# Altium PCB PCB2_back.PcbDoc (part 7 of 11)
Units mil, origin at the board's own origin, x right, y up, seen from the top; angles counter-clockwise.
Board outline 6299 x 3937 mil, 4 copper layers (TopLayer, GROUND, VCC, BottomLayer); 290 components, 470 nets, 2252 pads, 825 vias.
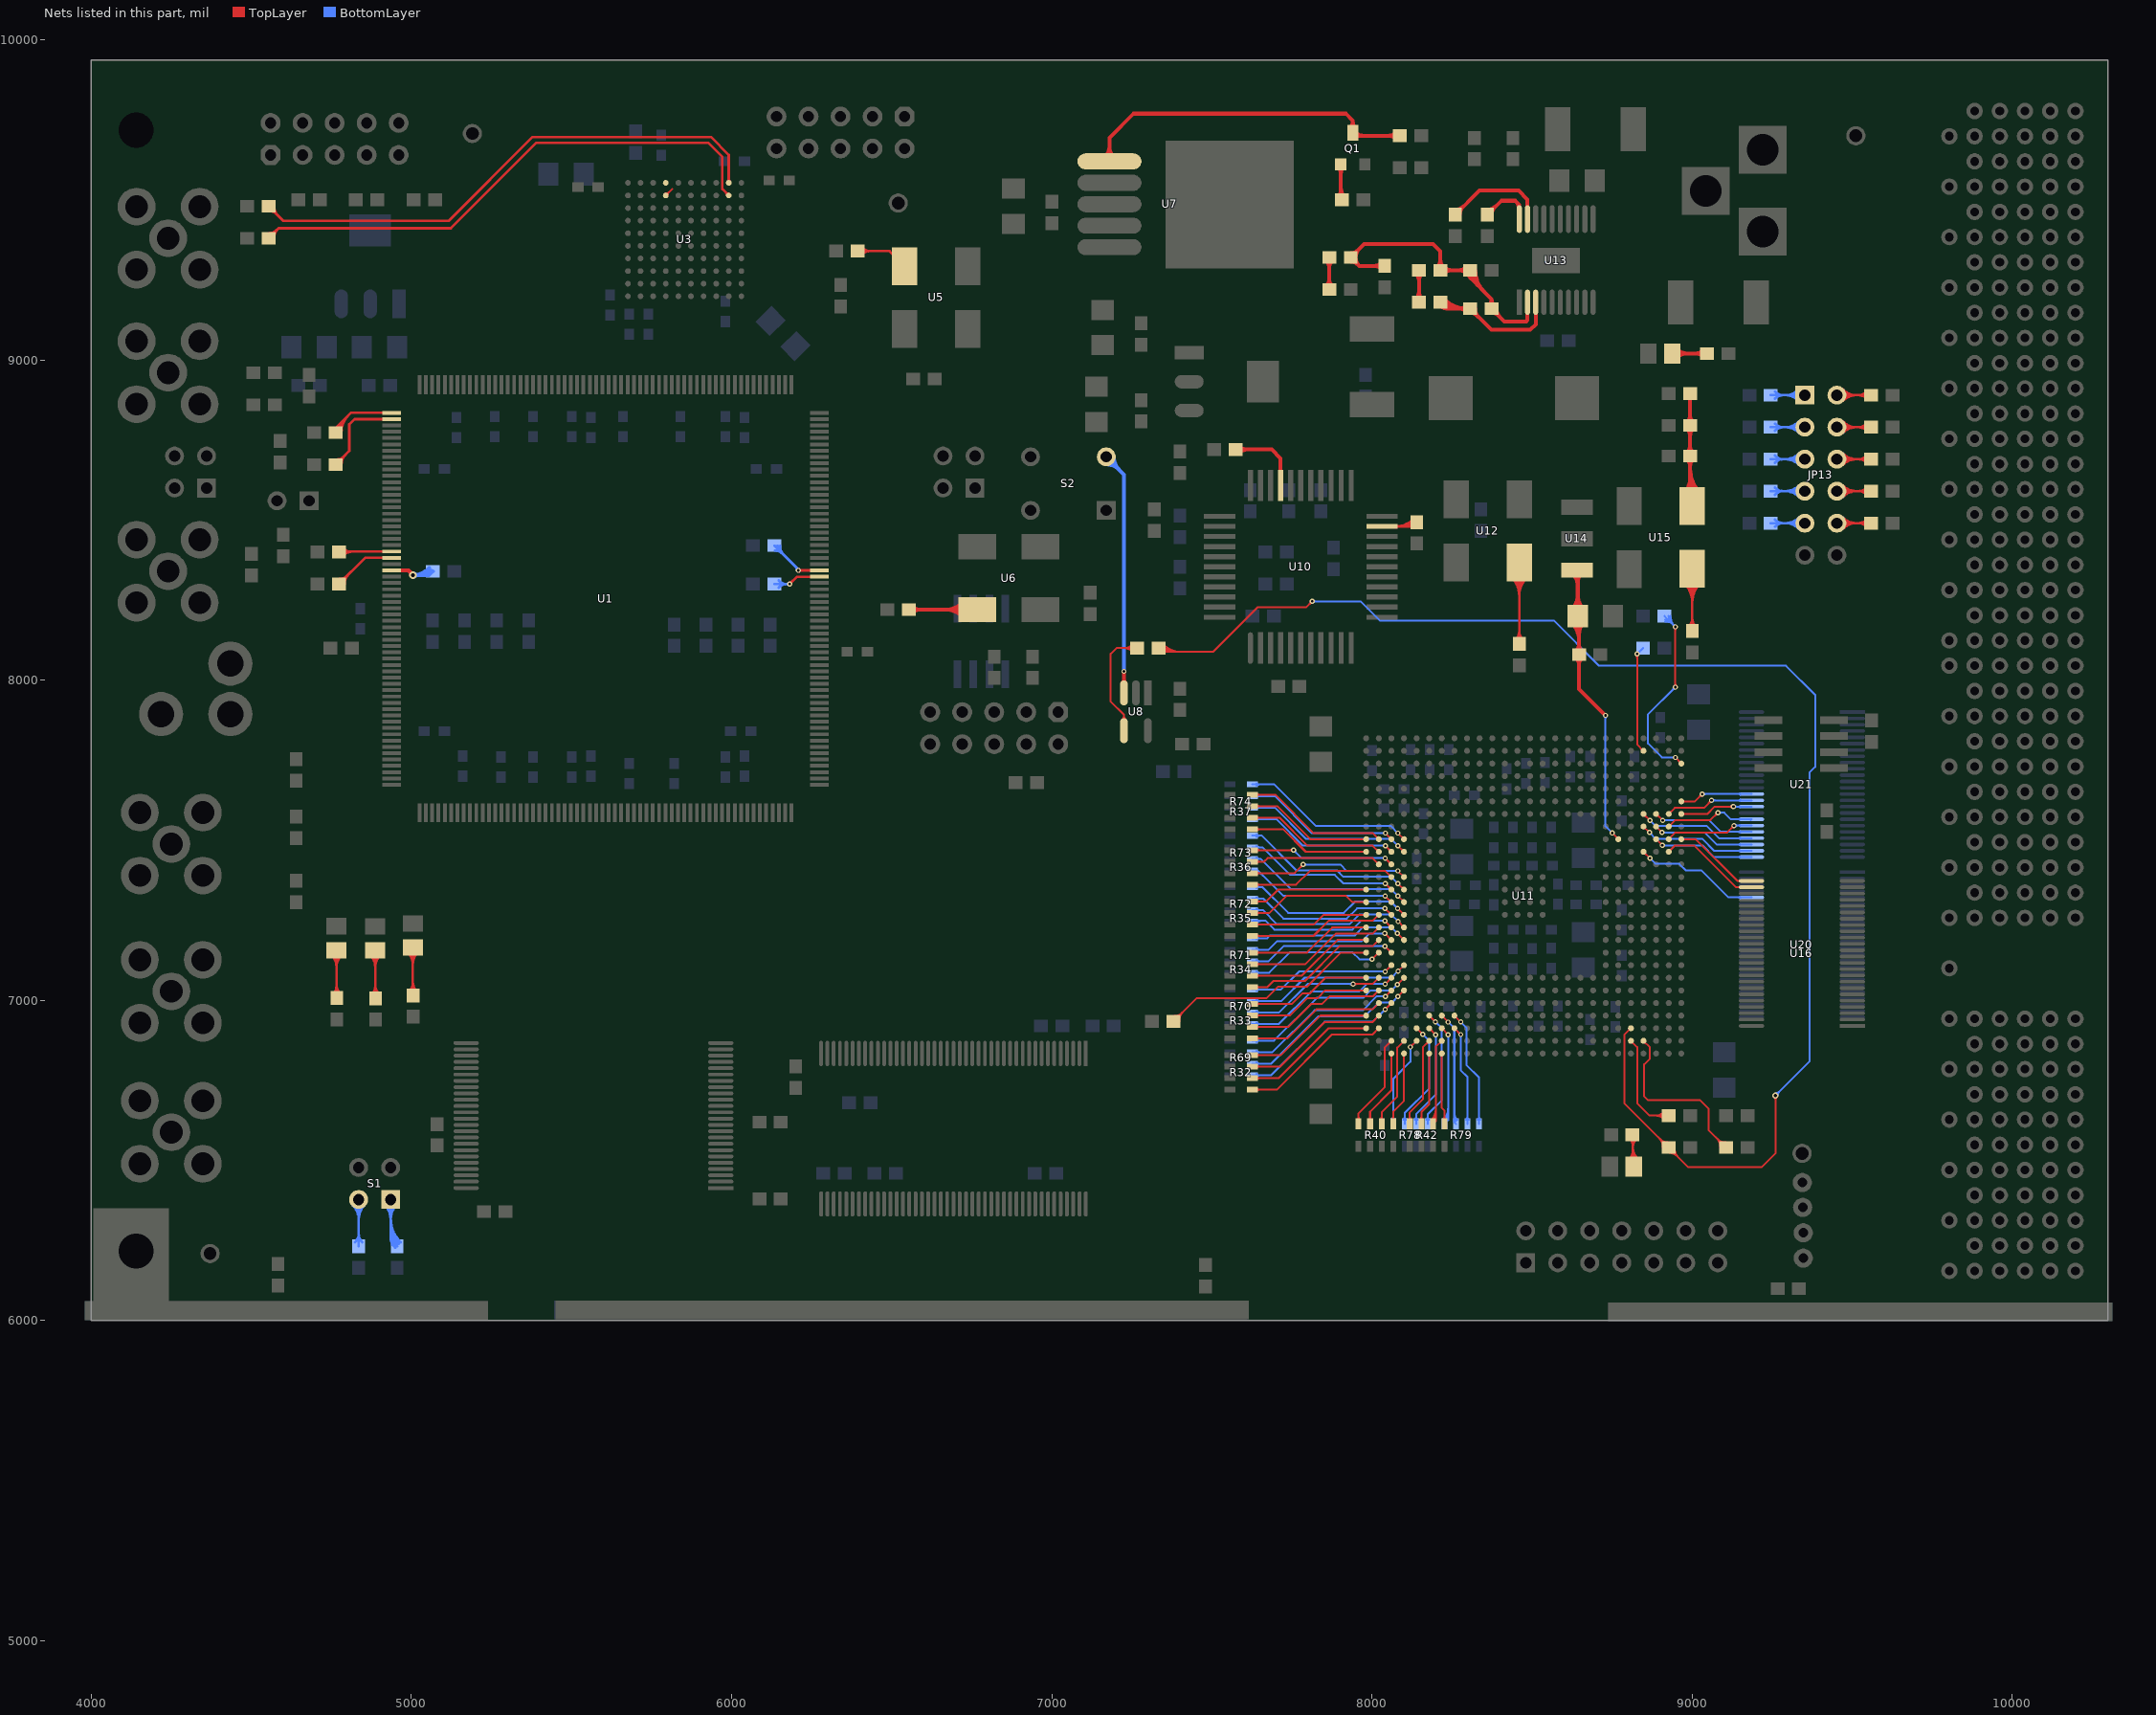
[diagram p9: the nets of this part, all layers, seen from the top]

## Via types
v1: diameter 16, hole 8, TopLayer to BottomLayer, 408 vias
v2: diameter 20, hole 10, TopLayer to BottomLayer, 221 vias
v3: diameter 24, hole 12, TopLayer to BottomLayer, 194 vias
v4: diameter 56.69, hole 56.69, TopLayer to BottomLayer, 2 vias

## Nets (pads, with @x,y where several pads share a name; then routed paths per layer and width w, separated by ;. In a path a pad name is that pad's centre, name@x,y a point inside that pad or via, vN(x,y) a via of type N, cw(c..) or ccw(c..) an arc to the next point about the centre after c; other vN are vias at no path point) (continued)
NetC113_1: C24.1 C25.1 C26.1 R41.1 R48.2 U13.2 | length 1527.5
  TopLayer w12: C24.1@7935.43,9306.31 cw(c7935.43,9278.03) 7955.43,9298.03 ; C24.1@7935.43,9333.69 ccw(c7935.43,9361.97) 7955.43,9341.97 ; C24.1@7949.11,9319.54 ccw(c7982.97,9318.41) 7959.01,9294.45 ; C24.1@7949.12,9320 cw(c7986.91,9320) 7960.19,9346.72 ; R41.1@8030.32,9283.79 ccw(c8006.96,9260.43) 8006.96,9293.46 ccw(c8006.96,9326.5) R41.1@8030.32,9303.14 ; R41.1@8040,9293.46 7960,9293.46 C24.1@7933.46,9320 7975.46,9362 8191,9362 8213.46,9339.54 C25.1@8213.46,9280 R48.2@8306.54,9280 8306.54,9256.46 ; C25.1@8203.79,9289.68 ccw(c8180.43,9313.04) 8213.46,9313.04 ccw(c8246.5,9313.04) C25.1@8223.14,9289.68 ; C25.1@8225.11,9270.32 cw(c8248.47,9246.96) 8248.47,9280 cw(c8248.47,9313.04) C25.1@8225.11,9289.68 ; R48.2@8294.89,9270.32 ccw(c8271.53,9246.96) 8271.53,9280 ccw(c8271.53,9313.04) R48.2@8294.89,9289.68 ; R48.2@8298.19,9280 ccw(c8334.86,9280) 8308.93,9254.07 ; R48.2@8299.77,9268.11 cw(c8293.14,9256.47) 8306.54,9256.47 ; R48.2@8300.22,9269.1 cw(c8290.56,9256.38) 8306.54,9256.38 cw(c8318.49,9256.38) R48.2@8313.83,9267.4 ; R48.2@8310.19,9280 ccw(c8375.83,9280) 8329.41,9233.59 ; R48.2@8313.3,9268.11 ccw(c8319.93,9256.47) 8306.54,9256.47 ; R48.2@8322.19,9280 ccw(c8416.8,9280) 8349.9,9213.1 ; C26.1@8364.62,9170.44 ccw(c8348.44,9189.53) 8373.46,9189.53 ; C26.1@8375.43,9146.31 cw(c8375.43,9118.03) 8395.43,9138.03 ; C26.1@8382.31,9170.44 cw(c8398.49,9189.53) 8373.46,9189.53 ; C26.1@8389.12,9160 ccw(c8426.91,9160) 8400.19,9133.28 ; U13.2@8485.59,9180 8485.59,9123.59 8482,9120 8413.46,9120 C26.1@8373.46,9160 8373.46,9189.54 ; 8306.54,9256.46 8373.46,9189.54
NetC113_2: C25.2 R47.1 | length 203.8
  TopLayer w12: R47.1@8136.86,9189.68 ccw(c8113.5,9213.04) 8146.54,9213.04 ccw(c8179.57,9213.04) R47.1@8156.21,9189.68 ; C25.2@8136.86,9270.32 cw(c8113.5,9246.96) 8146.54,9246.96 cw(c8179.57,9246.96) C25.2@8156.21,9270.32 ; R47.1@8146.54,9180 C25.2@8146.54,9280
NetC118_2: C26.2 R47.2 U13.3 | length 717
  TopLayer w12: R47.2@8208.14,9172.71 ccw(c8238.81,9203.38) 8238.81,9160 ; R47.2@8213.46,9180 8233.46,9160 C26.2@8306.54,9160 8372.54,9094 8494,9094 8511.18,9111.18 U13.3@8511.18,9180 ; R47.2@8216.62,9181.19 ccw(c8267.79,9232.35) 8267.79,9160 ; R47.2@8216.98,9166.4 cw(c8219.11,9147.62) 8232.48,9160.99 cw(c8243.38,9171.89) R47.2@8228.58,9176.18 ; R47.2@8225.11,9189.68 ccw(c8296.76,9261.32) C26.2@8296.76,9160 ; C26.2@8294.89,9150.32 ccw(c8271.53,9126.96) 8271.53,9160 ccw(c8271.53,9193.04) C26.2@8294.89,9169.68 ; C26.2@8308.5,9146.31 cw(c8308.5,9118.03) 8328.51,9138.03 ; C26.2@8322.19,9160 ccw(c8359.98,9160) 8333.26,9133.28
NetC122_2: C24.2 R38.1 | length 203.8
  TopLayer w12: R38.1@7856.86,9229.68 ccw(c7833.5,9253.04) 7866.54,9253.04 ccw(c7899.57,9253.04) R38.1@7876.21,9229.68 ; C24.2@7856.86,9310.32 cw(c7833.5,9286.96) 7866.54,9286.96 cw(c7899.57,9286.96) C24.2@7876.21,9310.32 ; R38.1@7866.54,9220 C24.2@7866.54,9320
NetC160_2: C33.2 C34.2 FB4.2 U15.4 | length 726.9
  TopLayer w12: U15.4@8976.37,8587.25 ccw(c8935.1,8628.4) 8993.38,8628.48 ; C33.2@8983.77,8709.66 ccw(c8960.83,8732.55) 8993.23,8732.59 ; C34.2@8983.77,8804.66 ccw(c8961.15,8827.22) 8993.1,8827.26 ; C33.2@8983.79,8690.32 cw(c8960.43,8666.96) 8993.46,8666.96 cw(c9026.5,8666.96) C33.2@9003.14,8690.32 ; C34.2@8983.79,8785.32 cw(c8960.43,8761.96) 8993.46,8761.96 cw(c9026.5,8761.96) C34.2@9003.14,8785.32 ; FB4.2@8993,8896 8993.46,8570.54 U15.4@9000,8564 ; 8993.1,8828.81 ccw(c9027.23,8828.86) C34.2@9003.13,8804.69 ; 8993.23,8733.48 ccw(c9026.9,8733.53) C33.2@9003.13,8709.69 ; 8993.34,8659.99 ccw(c9096.18,8660.14) U15.4@9023.56,8587.31 ; 8993.38,8631.02 ccw(c9067.25,8631.13) U15.4@9015.09,8578.82
NetC163_2: C29.1 C32.2 U11.V6 U14.3 | length 1373
  TopLayer w6: v1(8750,7522.44) U11.V6@8769.15,7503.29
  TopLayer w8: C29.1@8640,8202.57 C29.1@8642.57,8200 ; C32.2@8642.57,8083.97 C32.2@8646.54,8080
  TopLayer w12: C29.1@8624.54,8178.03 cw(c8571.43,8124.93) 8646.54,8124.93 ; C29.1@8624.54,8221.97 ccw(c8581.01,8265.49) 8642.57,8265.49 ccw(c8704.12,8265.49) C29.1@8660.6,8221.97 ; U14.3@8627.54,8330.69 cw(c8591.26,8294.41) 8642.57,8294.41 ; C29.1@8633.02,8186.52 cw(c8600.4,8153.9) 8646.54,8153.9 ; C29.1@8633.02,8213.48 ccw(c8609.98,8236.52) 8642.57,8236.52 ccw(c8675.15,8236.52) C29.1@8652.11,8213.48 ; C32.2@8636.86,8070.32 cw(c8613.5,8046.96) 8646.54,8046.96 cw(c8679.57,8046.96) C32.2@8656.21,8070.32 ; C32.2@8636.86,8089.68 ccw(c8613.5,8113.04) 8646.54,8113.04 ccw(c8679.57,8113.04) C32.2@8656.21,8089.68 ; U14.3@8640,8343.15 8642.57,8340.58 C29.1@8642.57,8200 8646.54,8196.03 8646.54,7972.46 v1(8729,7890) ; 8642.57,8306.8 cw(c8676.35,8306.8) U14.3@8652.46,8330.69 ; 8646.54,8144.09 cw(c8694.54,8144.09) C29.1@8660.6,8178.03
  BottomLayer w6: v1@8725.46,7886.46 cw(c8716.93,7877.93) 8729,7877.93 cw(c8741.07,7877.93) v1@8732.54,7886.46 ; v1(8729,7890) 8729,7543.44 v1(8750,7522.44)
NetDS1_2: DS3.2 R17.1 | length 359.7
  TopLayer w8: DS3.2@4988.73,7149.33 cw(c4951.88,7112.47) 5004,7112.47 cw(c5056.12,7112.47) DS3.2@5019.27,7149.33 ; R17.1@4993.91,7028.52 ccw(c4969.55,7052.89) 5004,7052.89 ; DS3.2@4994.39,7154.99 cw(c4971.19,7131.79) 5004,7131.79 cw(c5036.81,7131.79) DS3.2@5013.61,7154.99 ; 5004,7038.4 ccw(c5025.97,7038.4) R17.1@5010.43,7022.87 ; 5004,7057.71 ccw(c5045.28,7057.71) R17.1@5016.09,7028.52 ; DS3.2@5004,7164.6 5004,7016.46 R17.1@5005,7015.46
NetDS2_2: DS2.2 R16.1 | length 359.7
  TopLayer w8: DS2.2@4871.73,7140.33 cw(c4834.88,7103.47) 4887,7103.47 cw(c4939.12,7103.47) DS2.2@4902.27,7140.33 ; R16.1@4876.91,7019.52 ccw(c4852.55,7043.89) 4887,7043.89 ; DS2.2@4877.39,7145.99 cw(c4854.19,7122.79) 4887,7122.79 cw(c4919.81,7122.79) DS2.2@4896.61,7145.99 ; 4887,7029.4 ccw(c4908.97,7029.4) R16.1@4893.43,7013.87 ; 4887,7048.71 ccw(c4928.28,7048.71) R16.1@4899.09,7019.52 ; DS2.2@4887,7155.6 4887,7007.46 R16.1@4888,7006.46
NetDS3_2: DS1.2 R4.1 | length 359.7
  TopLayer w8: DS1.2@4750.73,7141.33 cw(c4713.88,7104.47) 4766,7104.47 cw(c4818.12,7104.47) DS1.2@4781.27,7141.33 ; R4.1@4755.91,7020.52 ccw(c4731.55,7044.89) 4766,7044.89 ; DS1.2@4756.39,7146.99 cw(c4733.19,7123.79) 4766,7123.79 cw(c4798.81,7123.79) DS1.2@4775.61,7146.99 ; 4766,7030.4 ccw(c4787.97,7030.4) R4.1@4772.43,7014.87 ; 4766,7049.71 ccw(c4807.28,7049.71) R4.1@4778.09,7020.52 ; DS1.2@4766,7156.6 4766,7008.46 R4.1@4767,7007.46
NetDS6_1: DS5.1 R57.1 | length 235.3
  TopLayer w12: DS5.1@8937.4,9020 R57.1@9046.54,9020 ; DS5.1@8951.25,9006.15 cw(c8984.7,8972.7) 8984.7,9020 cw(c8984.7,9067.3) DS5.1@8951.25,9033.85 ; R57.1@9034.89,9010.32 ccw(c9011.53,8986.96) 9011.53,9020 ccw(c9011.53,9053.04) R57.1@9034.89,9029.68
NetDS9_1: DS4.1 R51.2 | length 376.5
  TopLayer w6: DS4.1@8801.26,6501.71 ccw(c8769.51,6532.81) 8813.95,6533.27 ; R51.2@8803.76,6568.08 cw(c8780.28,6544.1) 8813.83,6544.45 ; DS4.1@8805.55,6497.51 ccw(c8784.15,6518.48) 8814.1,6518.79 ; R51.2@8807.96,6572.37 cw(c8794.61,6558.74) 8813.68,6558.94 ; R51.2@8813.46,6580 DS4.1@8814.46,6483.94 ; 8813.8,6547.55 ccw(c8878.43,6548.22) DS4.1@8833.21,6502.04 ; 8813.78,6549.43 cw(c8846.3,6549.77) R51.2@8823.07,6572.52 ; 8813.95,6533.06 ccw(c8864.1,6533.59) DS4.1@8829.01,6497.76 ; 8813.93,6534.95 cw(c8860.93,6535.44) R51.2@8827.35,6568.33 ; 8814.1,6518.58 ccw(c8849.77,6518.95) DS4.1@8824.81,6493.47
NetJP6_1: JP13.1 R85.1 | length 329.3
  BottomLayer w8: R85.1@9245.46,8890 JP13.1@9352,8890 ; R85.1@9258.52,8878.91 cw(c9285.3,8852.13) 9285.3,8890 cw(c9285.3,8927.87) R85.1@9258.52,8901.09 ; JP13.1@9333.95,8871.95 ccw(c9290.37,8828.37) 9290.37,8890 ccw(c9290.37,8951.63) JP13.1@9333.95,8908.05 ; JP13.1@9339.61,8877.61 ccw(c9309.68,8847.68) 9309.68,8890 ccw(c9309.68,8932.32) JP13.1@9339.61,8902.39
NetJP6_2: JP13.2 R62.2 | length 329.3
  TopLayer w8: JP13.2@9452,8890 R62.2@9558.54,8890 ; JP13.2@9464.39,8877.61 cw(c9494.32,8847.68) 9494.32,8890 cw(c9494.32,8932.32) JP13.2@9464.39,8902.39 ; JP13.2@9470.05,8871.95 cw(c9513.63,8828.37) 9513.63,8890 cw(c9513.63,8951.63) JP13.2@9470.05,8908.05 ; R62.2@9545.48,8878.91 ccw(c9518.7,8852.13) 9518.7,8890 ccw(c9518.7,8927.87) R62.2@9545.48,8901.09
NetJP6_3: JP13.3 R87.1 | length 329.3
  BottomLayer w8: R87.1@9245.46,8790 JP13.3@9352,8790 ; R87.1@9258.52,8778.91 cw(c9285.3,8752.13) 9285.3,8790 cw(c9285.3,8827.87) R87.1@9258.52,8801.09 ; JP13.3@9333.95,8771.95 ccw(c9290.37,8728.37) 9290.37,8790 ccw(c9290.37,8851.63) JP13.3@9333.95,8808.05 ; JP13.3@9339.61,8777.61 ccw(c9309.68,8747.68) 9309.68,8790 ccw(c9309.68,8832.32) JP13.3@9339.61,8802.39
NetJP6_4: JP13.4 R61.2 | length 329.3
  TopLayer w8: JP13.4@9452,8790 R61.2@9558.54,8790 ; JP13.4@9464.39,8777.61 cw(c9494.32,8747.68) 9494.32,8790 cw(c9494.32,8832.32) JP13.4@9464.39,8802.39 ; JP13.4@9470.05,8771.95 cw(c9513.63,8728.37) 9513.63,8790 cw(c9513.63,8851.63) JP13.4@9470.05,8808.05 ; R61.2@9545.48,8778.91 ccw(c9518.7,8752.13) 9518.7,8790 ccw(c9518.7,8827.87) R61.2@9545.48,8801.09
NetJP6_5: JP13.5 R86.1 | length 329.3
  BottomLayer w8: R86.1@9245.46,8690 JP13.5@9352,8690 ; R86.1@9258.52,8678.91 cw(c9285.3,8652.13) 9285.3,8690 cw(c9285.3,8727.87) R86.1@9258.52,8701.09 ; JP13.5@9333.95,8671.95 ccw(c9290.37,8628.37) 9290.37,8690 ccw(c9290.37,8751.63) JP13.5@9333.95,8708.05 ; JP13.5@9339.61,8677.61 ccw(c9309.68,8647.68) 9309.68,8690 ccw(c9309.68,8732.32) JP13.5@9339.61,8702.39
NetJP6_6: JP13.6 R60.2 | length 329.3
  TopLayer w8: JP13.6@9452,8690 R60.2@9558.54,8690 ; JP13.6@9464.39,8677.61 cw(c9494.32,8647.68) 9494.32,8690 cw(c9494.32,8732.32) JP13.6@9464.39,8702.39 ; JP13.6@9470.05,8671.95 cw(c9513.63,8628.37) 9513.63,8690 cw(c9513.63,8751.63) JP13.6@9470.05,8708.05 ; R60.2@9545.48,8678.91 ccw(c9518.7,8652.13) 9518.7,8690 ccw(c9518.7,8727.87) R60.2@9545.48,8701.09
NetJP6_7: JP13.7 R84.1 | length 329.3
  BottomLayer w8: R84.1@9245.46,8590 JP13.7@9352,8590 ; R84.1@9258.52,8578.91 cw(c9285.3,8552.13) 9285.3,8590 cw(c9285.3,8627.87) R84.1@9258.52,8601.09 ; JP13.7@9333.95,8571.95 ccw(c9290.37,8528.37) 9290.37,8590 ccw(c9290.37,8651.63) JP13.7@9333.95,8608.05 ; JP13.7@9339.61,8577.61 ccw(c9309.68,8547.68) 9309.68,8590 ccw(c9309.68,8632.32) JP13.7@9339.61,8602.39
NetJP6_8: JP13.8 R59.2 | length 329.3
  TopLayer w8: JP13.8@9452,8590 R59.2@9558.54,8590 ; JP13.8@9464.39,8577.61 cw(c9494.32,8547.68) 9494.32,8590 cw(c9494.32,8632.32) JP13.8@9464.39,8602.39 ; JP13.8@9470.05,8571.95 cw(c9513.63,8528.37) 9513.63,8590 cw(c9513.63,8651.63) JP13.8@9470.05,8608.05 ; R59.2@9545.48,8578.91 ccw(c9518.7,8552.13) 9518.7,8590 ccw(c9518.7,8627.87) R59.2@9545.48,8601.09
NetJP6_9: JP13.9 R83.1 | length 329.3
  BottomLayer w8: R83.1@9245.46,8490 JP13.9@9352,8490 ; R83.1@9258.52,8478.91 cw(c9285.3,8452.13) 9285.3,8490 cw(c9285.3,8527.87) R83.1@9258.52,8501.09 ; JP13.9@9333.95,8471.95 ccw(c9290.37,8428.37) 9290.37,8490 ccw(c9290.37,8551.63) JP13.9@9333.95,8508.05 ; JP13.9@9339.61,8477.61 ccw(c9309.68,8447.68) 9309.68,8490 ccw(c9309.68,8532.32) JP13.9@9339.61,8502.39
NetJP6_10: JP13.10 R58.2 | length 329.3
  TopLayer w8: JP13.10@9452,8490 R58.2@9558.54,8490 ; JP13.10@9464.39,8477.61 cw(c9494.32,8447.68) 9494.32,8490 cw(c9494.32,8532.32) JP13.10@9464.39,8502.39 ; JP13.10@9470.05,8471.95 cw(c9513.63,8428.37) 9513.63,8490 cw(c9513.63,8551.63) JP13.10@9470.05,8508.05 ; R58.2@9545.48,8478.91 ccw(c9518.7,8452.13) 9518.7,8490 ccw(c9518.7,8527.87) R58.2@9545.48,8501.09
NetQ1_1: Q1.1 R46.1 U7.1 | length 1294.2
  TopLayer w12: U7.1@7193.44,9633.44 cw(c7225.87,9665.87) 7180,9665.87 cw(c7134.13,9665.87) 7166.56,9633.44 U7.1@7180,9620 7180,9694 7255,9769 7918,9769 7940,9747 Q1.1@7940,9709.21 7949.21,9700 R46.1@8086.54,9700 ; Q1.1@7931.72,9724.78 ccw(c7911.71,9744.78) 7940,9744.78 ccw(c7968.29,9744.78) Q1.1@7948.28,9724.78 ; Q1.1@7948.28,9693.64 cw(c7963.63,9678.3) 7963.63,9700 ; Q1.1@7948.28,9710.21 ccw(c7972.94,9734.87) 7972.94,9700 ; R46.1@8074.89,9690.32 ccw(c8051.53,9666.96) 8051.53,9700 ccw(c8051.53,9733.04) R46.1@8074.89,9709.68
NetQ1_2: Q1.2 R39.1 | length 208.7
  TopLayer w12: Q1.2@7894.31,9601.52 cw(c7874.31,9581.52) 7902.6,9581.52 cw(c7930.88,9581.52) Q1.2@7910.88,9601.52 ; R39.1@7894.89,9509.68 ccw(c7876.28,9528.29) 7902.6,9528.29 ; 7902.6,9537.79 ccw(c7942.36,9537.79) R39.1@7914.24,9509.68 ; Q1.2@7902.6,9610.79 7902.6,9503.94 R39.1@7906.54,9500
NetR2_2: R11.2 U1.122 | length 359.7
  TopLayer w8: R11.2@4763.46,8673 4806,8715.54 4806,8799 4822.02,8815.02 U1.122@4937.69,8815.02 ; R11.2@4765.43,8688.68 ccw(c4765.43,8721.8) 4788.85,8698.38 ; R11.2@4773.12,8673 cw(c4796.42,8673) R11.2@4779.94,8689.48 ; R11.2@4781.12,8673 cw(c4823.74,8673) 4793.6,8703.14
NetR3_2: R12.2 U1.121 | length 345.5
  TopLayer w8: R12.2@4763.46,8773 4763.46,8787.46 4810.71,8834.71 U1.121@4937.69,8834.71 ; R12.2@4765.12,8773 cw(c4804.03,8773) 4776.52,8800.52 ; R12.2@4773.12,8773 cw(c4831.34,8773) 4790.17,8814.17 ; R12.2@4781.12,8773 cw(c4858.66,8773) 4803.83,8827.83
NetR6_2: R9.2 U1.144 | length 276
  TopLayer w8: R9.2@4773.46,8300 4855.42,8381.95 U1.144@4937.69,8381.95 ; R9.2@4775.43,8315.68 ccw(c4775.43,8348.8) 4798.85,8325.38 ; R9.2@4783.12,8300 cw(c4806.42,8300) R9.2@4789.94,8316.48 ; R9.2@4791.12,8300 cw(c4833.74,8300) 4803.6,8330.14
NetR7_2: R10.2 U1.143 | length 243.4
  TopLayer w8: R10.2@4773.46,8400 4775.1,8401.64 U1.143@4937.69,8401.64 ; R10.2@4780.87,8394.57 cw(c4797.94,8377.49) 4797.94,8401.64 ; R10.2@4786.52,8388.91 cw(c4817.25,8358.18) 4817.25,8401.64 ; R10.2@4786.52,8411.09 ccw(c4809.35,8433.91) 4809.35,8401.64
NetR22_2: R67.2 U1.34 | length 240.1
  TopLayer w8: v1(6181,8300) 6203.9,8322.9 U1.34@6274.31,8322.9 ; v1@6181,8304 ccw(c6181,8313.66) 6187.83,8306.83 ccw(c6194.66,8300) v1@6185,8300
  BottomLayer w8: R67.2@6133.46,8300 v1(6181,8300) ; R67.2@6146.52,8288.91 cw(c6173.3,8262.13) 6173.3,8300 cw(c6173.3,8337.87) R67.2@6146.52,8311.09 ; v1@6178.17,8297.17 ccw(c6171.34,8290.34) 6171.34,8300 ccw(c6171.34,8309.66) v1@6178.17,8302.83
NetR23_2: R68.2 U1.35 | length 282.8
  TopLayer w8: v1(6208.58,8342.58) U1.35@6274.31,8342.58 ; v1@6211.41,8339.75 cw(c6218.24,8332.93) 6218.24,8342.58 cw(c6218.24,8352.24) v1@6211.41,8345.41
  BottomLayer w8: R68.2@6133.46,8420 6208.58,8344.88 v1(6208.58,8342.58) v1@6206,8340 ; R68.2@6135.43,8404.32 cw(c6135.43,8371.2) 6158.85,8394.62 ; R68.2@6143.12,8420 ccw(c6166.42,8420) R68.2@6149.94,8403.52 ; R68.2@6151.12,8420 ccw(c6193.74,8420) 6163.6,8389.86 ; 6200.13,8353.34 cw(c6189.37,8342.58) v1@6204.58,8342.58
NetR24_1: R23.1 U6.3 | length 473.2
  TopLayer w12: R23.1@6553.46,8220 U6.3@6767.15,8220 ; R23.1@6565.11,8210.32 cw(c6588.47,8186.96) 6588.47,8220 cw(c6588.47,8253.04) R23.1@6565.11,8229.68 ; U6.3@6723.87,8196.4 ccw(c6666.9,8139.44) 6666.9,8220 ccw(c6666.9,8300.56) U6.3@6723.87,8243.6 ; U6.3@6732.35,8204.89 ccw(c6695.87,8168.41) 6695.87,8220 ccw(c6695.87,8271.59) U6.3@6732.35,8235.11
NetR25_1: R22.1 U5.3 | length 225.5
  TopLayer w8: R22.1@6393.46,9340 6492.85,9340 U5.3@6540,9292.85 ; R22.1@6406.52,9328.91 cw(c6433.3,9302.13) 6433.3,9340 cw(c6433.3,9377.87) R22.1@6406.52,9351.09
NetR30_1: R34.1 U11.K25 | length 478.9
  TopLayer w6: R34.1@7626,7041 7673,7041 7692.45,7060.45 7790.45,7060.45 7899,7169 8001.79,7169 U11.K25@8021.12,7188.33 ; R34.1@7638.74,7036.76 cw(c7648.99,7026.51) 7648.99,7041 cw(c7648.99,7055.49) R34.1@7638.74,7045.24
NetR30_2: R34.2 U11.K26 | length 424.6
  TopLayer w6: R34.2@7626,7077 7781,7077 7892.33,7188.33 U11.K26@7981.75,7188.33 ; R34.2@7638.74,7072.76 cw(c7648.99,7062.51) 7648.99,7077 cw(c7648.99,7091.49) R34.2@7638.74,7081.24
NetR30_3: R34.3 U11.L25 | length 465.4
  TopLayer w6: R34.3@7626,7113 7792,7113 7887,7208 8001.42,7208 U11.L25@8021.12,7227.7 ; R34.3@7638.74,7108.76 cw(c7648.99,7098.51) 7648.99,7113 cw(c7648.99,7127.49) R34.3@7638.74,7117.24
NetR30_4: R34.4 U11.L26 | length 411.1
  TopLayer w6: R34.4@7626,7149 7797,7149 7875.7,7227.7 U11.L26@7981.75,7227.7 ; R34.4@7638.74,7144.76 cw(c7648.99,7134.51) 7648.99,7149 cw(c7648.99,7163.49) R34.4@7638.74,7153.24
NetR31_1: R40.1 U11.A23 | length 256.8
  TopLayer w6: R40.1@8061.76,6626.74 ccw(c8051.51,6636.99) 8066,6636.99 ccw(c8080.49,6636.99) R40.1@8070.24,6626.74 ; R40.1@8066,6614 8066,6652 8099.86,6685.86 U11.A23@8099.86,6834
NetR31_2: R40.2 U11.B23 | length 311.1
  TopLayer w6: R40.2@8025.76,6626.74 ccw(c8015.51,6636.99) 8030,6636.99 ccw(c8044.49,6636.99) R40.2@8034.24,6626.74 ; R40.2@8030,6614 8030,6650 8079,6699 8079,6852.51 U11.B23@8099.86,6873.37
NetR31_3: R40.3 U11.A24 | length 270.3
  TopLayer w6: R40.3@7989.76,6626.74 ccw(c7979.51,6636.99) 7994,6636.99 ccw(c8008.49,6636.99) R40.3@7998.24,6626.74 ; R40.3@7994,6614 7994,6652 8060.49,6718.49 U11.A24@8060.49,6834
NetR31_4: R40.4 U11.B24 | length 324.6
  TopLayer w6: R40.4@7953.76,6626.74 ccw(c7943.51,6636.99) 7958,6636.99 ccw(c7972.49,6636.99) R40.4@7962.24,6626.74 ; R40.4@7958,6614 7958,6647 8040,6729 8040,6852.88 U11.B24@8060.49,6873.37
NetR32_1: R42.1 U11.A20 | length 246.1
  TopLayer w6: U11.A20@8217.97,6834 8217.97,6664.03 8226,6656 R42.1@8226,6614 ; R42.1@8221.76,6626.74 ccw(c8211.51,6636.99) 8226,6636.99 ccw(c8240.49,6636.99) R42.1@8230.24,6626.74
NetR32_2: R42.2 U11.B20 | length 343.4
  TopLayer w6: R42.2@8185.76,6626.74 ccw(c8153.79,6658.71) 8199,6658.71 ; R42.2@8190,6614 8199,6623 8199,6854.4 U11.B20@8217.97,6873.37 ; R42.2@8190,6622.5 ccw(c8168.27,6644.23) 8199,6644.23 ; R42.2@8194.24,6618.26 ccw(c8182.76,6629.74) 8199,6629.74
NetR32_3: R42.3 U11.A21 | length 252.9
  TopLayer w6: R42.3@8149.76,6626.74 ccw(c8139.51,6636.99) 8154,6636.99 ccw(c8168.49,6636.99) R42.3@8158.24,6626.74 ; R42.3@8154,6614 8154,6651 8178.6,6675.6 U11.A21@8178.6,6834
NetR32_4: R42.4 U11.B21 | length 307.2
  TopLayer w6: R42.4@8113.76,6626.74 ccw(c8103.51,6636.99) 8118,6636.99 ccw(c8132.49,6636.99) R42.4@8122.24,6626.74 ; R42.4@8118,6614 8118,6650 8159,6691 8159,6853.77 U11.B21@8178.6,6873.37
NetR33_1: R78.1 U11.B22 | length 312.5
  TopLayer w6: v1(8120,6854.14) U11.B22@8139.23,6873.37
  BottomLayer w6: R78.1@8061.76,6626.74 ccw(c8051.51,6636.99) 8066,6636.99 ccw(c8080.49,6636.99) R78.1@8070.24,6626.74 ; R78.1@8066,6614 8066,6754 8120,6808 v1(8120,6854.14)
NetR33_2: R78.2 U11.C22 | length 369.9
  TopLayer w6: U11.C22@8139.23,6912.74 v1(8158,6893.97)
  BottomLayer w6: R78.2@8097.76,6626.74 ccw(c8087.51,6636.99) 8102,6636.99 ccw(c8116.49,6636.99) R78.2@8106.24,6626.74 ; R78.2@8102,6614 8102,6648 8179,6725 8179,6872.97 v1(8158,6893.97)
NetR33_3: R78.3 U11.C21 | length 355.2
  TopLayer w6: U11.C21@8178.6,6912.74 v1(8199,6892.34)
  BottomLayer w6: R78.3@8133.76,6626.74 ccw(c8123.51,6636.99) 8138,6636.99 ccw(c8152.49,6636.99) R78.3@8142.24,6626.74 ; R78.3@8138,6614 8138,6644 8199,6705 v1(8199,6892.34)
NetR33_4: R78.4 U11.D21 | length 395.4
  TopLayer w6: U11.D21@8178.6,6952.11 v1(8198,6932.71)
  BottomLayer w6: R78.4@8169.76,6626.74 ccw(c8159.51,6636.99) 8174,6636.99 ccw(c8188.49,6636.99) R78.4@8178.24,6626.74 ; R78.4@8174,6614 8174,6644 8218,6688 8218,6912.71 v1(8198,6932.71)
NetR34_1: R79.1 U11.C20 | length 408.5
  TopLayer w6: U11.C20@8217.97,6912.74 v1(8238,6892.71)
  BottomLayer w6: R79.1@8221.76,6626.74 ccw(c8182.54,6665.96) 8238,6665.96 ; R79.1@8226,6614 8238,6626 v1(8238,6892.71) ; R79.1@8226,6622.5 ccw(c8197.03,6651.47) 8238,6651.47 ; R79.1@8230.24,6618.26 ccw(c8211.51,6636.99) 8238,6636.99
NetR34_2: R79.2 U11.D20 | length 394.5
  TopLayer w6: U11.D20@8217.97,6952.11 v1(8238,6932.08)
  BottomLayer w6: v1(8238,6932.08) 8257,6913.08 8257,6619 R79.2@8262,6614 ; 8257,6634.57 ccw(c8274.07,6634.57) R79.2@8262,6622.5 ; 8257,6649.06 ccw(c8288.56,6649.06) R79.2@8266.24,6626.74
NetR34_3: R79.3 U11.C19 | length 338.3
  TopLayer w6: U11.C19@8257.34,6912.74 v1(8277,6893)
  BottomLayer w6: v1(8277,6893) 8277,6782 8298,6761 R79.3@8298,6614 ; R79.3@8293.76,6626.74 ccw(c8283.51,6636.99) 8298,6636.99 ccw(c8312.49,6636.99) R79.3@8302.24,6626.74
NetR34_4: R79.4 U11.D19 | length 392.6
  TopLayer w6: U11.D19@8257.34,6952.11 v1(8277,6932.45)
  BottomLayer w6: v1(8277,6932.45) 8295,6914.45 8295,6798 8334,6759 R79.4@8334,6614 ; R79.4@8329.76,6626.74 ccw(c8319.51,6636.99) 8334,6636.99 ccw(c8348.49,6636.99) R79.4@8338.24,6626.74
NetR35_1: R70.1 U11.H24 | length 488.6
  TopLayer w6: v1(8040.9,7090) U11.H24@8060.49,7109.59
  BottomLayer w6: R70.1@7626,7034 7716,7034 7772,7090 v1(8040.9,7090) ; R70.1@7638.74,7029.76 cw(c7648.99,7019.51) 7648.99,7034 cw(c7648.99,7048.49) R70.1@7638.74,7038.24
NetR35_2: R70.2 U11.H23 | length 542.8
  TopLayer w6: v1(8081.27,7091) U11.H23@8099.86,7109.59
  BottomLayer w6: R70.2@7626,6998 7717,6998 7790,7071 8061.27,7071 v1(8081.27,7091) ; R70.2@7638.74,6993.76 cw(c7648.99,6983.51) 7648.99,6998 cw(c7648.99,7012.49) R70.2@7638.74,7002.24
NetR35_3: R70.3 U11.G25 | length 500.6
  TopLayer w6: v1(7941,7051) 8001.9,7051 U11.G25@8021.12,7070.22 ; v1@7944.54,7047.46 cw(c7953.07,7038.93) 7953.07,7051 cw(c7953.07,7063.07) v1@7944.54,7054.54
  BottomLayer w6: R70.3@7626,6962 7710,6962 7799,7051 v1(7941,7051) ; R70.3@7638.74,6957.76 cw(c7648.99,6947.51) 7648.99,6962 cw(c7648.99,6976.49) R70.3@7638.74,6966.24 ; v1@7937.46,7047.46 ccw(c7928.93,7038.93) 7928.93,7051 ccw(c7928.93,7063.07) v1@7937.46,7054.54
NetR35_4: R70.4 U11.G24 | length 517
  TopLayer w6: v1(8041.27,7051) U11.G24@8060.49,7070.22
  BottomLayer w6: R70.4@7626,6926 7709,6926 7810,7027 7960,7027 7984,7051 v1(8041.27,7051) ; R70.4@7638.74,6921.76 cw(c7648.99,6911.51) 7648.99,6926 cw(c7648.99,6940.49) R70.4@7638.74,6930.24
NetR36_1: R69.1 U11.G23 | length 578.1
  TopLayer w6: v1(8079,7049) 8099.86,7069.86 U11.G23@8099.86,7070.22
  BottomLayer w6: R69.1@7626,6874 7694,6874 7828,7008 7973,7008 7996,7031 8061,7031 v1(8079,7049) ; R69.1@7638.74,6869.76 cw(c7648.99,6859.51) 7648.99,6874 cw(c7648.99,6888.49) R69.1@7638.74,6878.24
NetR36_2: R69.2 U11.F24 | length 537.1
  TopLayer w6: v1(8041.64,7012) U11.F24@8060.49,7030.85
  BottomLayer w6: R69.2@7626,6838 7689,6838 7820,6969 7971,6969 8014,7012 v1(8041.64,7012) ; R69.2@7638.74,6833.76 cw(c7648.99,6823.51) 7648.99,6838 cw(c7648.99,6852.49) R69.2@7638.74,6842.24
NetR36_3: R69.3 U11.F23 | length 591.4
  TopLayer w6: v1(8081.01,7012) U11.F23@8099.86,7030.85
  BottomLayer w6: R69.3@7626,6802 7685,6802 7833,6950 7978,6950 8021,6993 8062.01,6993 v1(8081.01,7012) ; R69.3@7638.74,6797.76 cw(c7648.99,6787.51) 7648.99,6802 cw(c7648.99,6816.49) R69.3@7638.74,6806.24
NetR36_4: R69.4 U11.E24 | length 550.6
  TopLayer w6: v1(8041.01,6972) U11.E24@8060.49,6991.48
  BottomLayer w6: R69.4@7626,6766 7685,6766 7852,6933 8002.01,6933 v1(8041.01,6972) ; R69.4@7638.74,6761.76 cw(c7648.99,6751.51) 7648.99,6766 cw(c7648.99,6780.49) R69.4@7638.74,6770.24
NetR37_1: R33.1 U11.E25 | length 463.6
  TopLayer w6: R33.1@7626,6881 7735,6881 7826,6972 8001.64,6972 U11.E25@8021.12,6991.48 ; R33.1@7638.74,6876.76 cw(c7648.99,6866.51) 7648.99,6881 cw(c7648.99,6895.49) R33.1@7638.74,6885.24
NetR37_2: R33.2 U11.F25 | length 465
  TopLayer w6: R33.2@7626,6917 7739,6917 7811,6989 7844,6989 7867,7012 8002.27,7012 U11.F25@8021.12,7030.85 ; R33.2@7638.74,6912.76 cw(c7648.99,6902.51) 7648.99,6917 cw(c7648.99,6931.49) R33.2@7638.74,6921.24
NetR37_3: R33.3 U11.F26 | length 410.7
  TopLayer w6: R33.3@7626,6953 7744.15,6953 7797.15,7006 7829,7006 7853.85,7030.85 U11.F26@7981.75,7030.85 ; R33.3@7638.74,6948.76 cw(c7648.99,6938.51) 7648.99,6953 cw(c7648.99,6967.49) R33.3@7638.74,6957.24
NetR37_4: R33.4 U11.G26 | length 412.1
  TopLayer w6: R33.4@7626,6989 7750,6989 7782,7021 7805,7021 7854.22,7070.22 U11.G26@7981.75,7070.22 ; R33.4@7638.74,6984.76 cw(c7648.99,6974.51) 7648.99,6989 cw(c7648.99,7003.49) R33.4@7638.74,6993.24
NetR38_1: R32.1 U11.C25 | length 497.3
  TopLayer w6: R32.1@7626,6721 7703,6721 7875,6893 8001.38,6893 U11.C25@8021.12,6912.74 ; R32.1@7638.74,6716.76 cw(c7648.99,6706.51) 7648.99,6721 cw(c7648.99,6735.49) R32.1@7638.74,6725.24
NetR38_2: R32.2 U11.C26 | length 446.9
  TopLayer w6: R32.2@7628.74,6759.74 R32.2@7626,6757 7709,6757 7864.74,6912.74 U11.C26@7981.75,6912.74 ; R32.2@7638.74,6752.76 cw(c7648.99,6742.51) 7648.99,6757 cw(c7648.99,6771.49) R32.2@7638.74,6761.24
NetR38_3: R32.3 U11.D25 | length 483.8
  TopLayer w6: R32.3@7626,6793 7713,6793 7852,6932 8001.01,6932 U11.D25@8021.12,6952.11 ; R32.3@7638.74,6788.76 cw(c7648.99,6778.51) 7648.99,6793 cw(c7648.99,6807.49) R32.3@7638.74,6797.24
NetR38_4: R32.4 U11.D26 | length 429.5
  TopLayer w6: R32.4@7626,6829 7716,6829 7839.11,6952.11 U11.D26@7981.75,6952.11 ; R32.4@7638.74,6824.76 cw(c7648.99,6814.51) 7648.99,6829 cw(c7648.99,6843.49) R32.4@7638.74,6833.24
NetR39_1: R43.1 U10.21 | length 265.7
  TopLayer w8: U10.21@8031.42,8479.92 8126.46,8479.92 R43.1@8140,8493.46 ; U10.21@8074.19,8479.92 ccw(c8074.19,8557.31) R43.1@8128.91,8502.59 ; U10.21@8075.5,8477.18 cw(c8082.11,8470.57) 8082.11,8479.92 cw(c8082.11,8489.27) U10.21@8075.5,8482.66 ; 8093.5,8479.92 ccw(c8093.5,8537.99) R43.1@8134.57,8496.93 ; 8112.82,8479.92 ccw(c8112.82,8518.68) R43.1@8140.22,8491.27
NetR40_1: R31.1 U10.30 | length 288.9
  TopLayer w12: R31.1@7573.46,8720 7687,8720 7714.49,8692.51 U10.30@7714.49,8607.87 ; R31.1@7585.11,8710.32 cw(c7608.47,8686.96) 7608.47,8720 cw(c7608.47,8753.04) R31.1@7585.11,8729.68
NetR47_1: R72.1 U11.M23 | length 553.8
  TopLayer w6: v1(8079.93,7287) U11.M23@8099.86,7267.07
  BottomLayer w6: R72.1@7638.74,7349.76 cw(c7648.99,7339.51) 7648.99,7354 cw(c7648.99,7368.49) R72.1@7638.74,7358.24 ; R72.1@7639.92,7351.42 cw(c7644,7349.48) 7644,7354 ; R72.1@7639.92,7356.58 ccw(c7644,7358.52) 7644,7354 ; v1(8079.93,7287) 8058.93,7308 7947,7308 7912,7273 7738,7273 7657,7354 7644,7354
NetR47_2: R72.2 U11.M24 | length 504.8
  TopLayer w6: v1(8040.56,7287) U11.M24@8060.49,7267.07
  BottomLayer w6: R72.2@7626,7318 7660,7318 7723,7255 7921,7255 7953,7287 v1(8040.56,7287) ; R72.2@7638.74,7313.76 cw(c7648.99,7303.51) 7648.99,7318 cw(c7648.99,7332.49) R72.2@7638.74,7322.24
NetR47_3: R72.3 U11.L23 | length 544
  TopLayer w6: v1(8081.56,7246) U11.L23@8099.86,7227.7
  BottomLayer w6: R72.3@7626,7282 7659,7282 7703,7238 7930,7238 7960,7268 8059.56,7268 v1(8081.56,7246) ; R72.3@7638.74,7277.76 cw(c7648.99,7267.51) 7648.99,7282 cw(c7648.99,7296.49) R72.3@7638.74,7286.24
NetR47_4: R72.4 U11.L24 | length 488.8
  TopLayer w6: v1(8040.19,7248) U11.L24@8060.49,7227.7
  BottomLayer w6: R72.4@7626,7246 7628,7248 7668,7248 7695,7221 7939,7221 7966,7248 v1(8040.19,7248) ; R72.4@7638.74,7241.76 cw(c7653.81,7226.69) 7653.81,7248 ; R72.4@7638.74,7250.24 ccw(c7644.16,7255.66) 7644.16,7248
NetR48_1: R73.1 U11.P23 | length 566.3
  TopLayer w6: v1(8080.67,7365) U11.P23@8099.86,7345.81
  BottomLayer w6: R73.1@7626,7514 7656,7514 7764.29,7405.71 7890.29,7405.71 7910,7386 8059.67,7386 v1(8080.67,7365) ; R73.1@7638.74,7509.76 cw(c7648.99,7499.51) 7648.99,7514 cw(c7648.99,7528.49) R73.1@7638.74,7518.24
NetR48_2: R73.2 U11.P24 | length 512
  TopLayer w6: v1(8041.3,7365) U11.P24@8060.49,7345.81
  BottomLayer w6: R73.2@7626,7478 7658,7478 7743.96,7392.04 7883.96,7392.04 7911,7365 v1(8041.3,7365) ; R73.2@7638.74,7473.76 cw(c7648.99,7463.51) 7648.99,7478 cw(c7648.99,7492.49) R73.2@7638.74,7482.24
NetR48_3: R73.3 U11.N23 | length 553.2
  TopLayer w6: v1(8081,7326) 8099.86,7307.14 U11.N23@8099.86,7306.44
  BottomLayer w6: R73.3@7626,7442 7652,7442 7747,7347 8060,7347 v1(8081,7326) ; R73.3@7638.74,7437.76 cw(c7648.99,7427.51) 7648.99,7442 cw(c7648.99,7456.49) R73.3@7638.74,7446.24
NetR48_4: R73.4 U11.N24 | length 519.3
  TopLayer w6: v1(8040.93,7326) U11.N24@8060.49,7306.44
  BottomLayer w6: R73.4@7626,7406 7643,7406 7723,7326 v1(8040.93,7326) ; R73.4@7634.5,7400 cw(c7634.5,7364.99) 7659.25,7389.75 ; R73.4@7634.5,7406 cw(c7634.5,7385.48) 7649.01,7399.99
NetR49_1: R36.1 U11.R24 | length 482.8
  TopLayer w6: R36.1@7626,7361 7763,7361 7806,7404 8041.67,7404 U11.R24@8060.49,7385.18 ; R36.1@7638.74,7356.76 cw(c7648.99,7346.51) 7648.99,7361 cw(c7648.99,7375.49) R36.1@7638.74,7365.24
NetR49_2: R36.2 U11.R23 | length 561.8
  TopLayer w6: R36.2@7626,7397 7758,7397 v1(7785,7424) ; R36.2@7638.74,7392.76 cw(c7648.99,7382.51) 7648.99,7397 cw(c7648.99,7411.49) R36.2@7638.74,7401.24 ; v1@7780,7424 cw(c7767.93,7424) 7776.46,7415.46 cw(c7785,7406.93) v1@7785,7419 ; v1(8081.04,7404) U11.R23@8099.86,7385.18
  BottomLayer w6: v1(7785,7424) 7901,7424 7921,7404 v1(8081.04,7404) ; v1@7788.54,7420.46 cw(c7797.07,7411.93) 7797.07,7424 cw(c7797.07,7436.07) v1@7788.54,7427.54
NetR49_3: R36.3 U11.T25 | length 430.5
  TopLayer w6: R36.3@7626,7433 7663,7433 7674,7444 8001.67,7444 U11.T25@8021.12,7424.55 ; R36.3@7638.74,7428.76 cw(c7648.99,7418.51) 7648.99,7433 cw(c7648.99,7447.49) R36.3@7638.74,7437.24
NetR49_4: R36.4 U11.T24 | length 513.6
  TopLayer w6: R36.4@7626,7469 v1(7755,7469) ; R36.4@7638.74,7464.76 cw(c7648.99,7454.51) 7648.99,7469 cw(c7648.99,7483.49) R36.4@7638.74,7473.24 ; v1@7751.46,7465.46 ccw(c7742.93,7456.93) 7742.93,7469 ccw(c7742.93,7481.07) v1@7751.46,7472.54 ; v1(8041.04,7444) U11.T24@8060.49,7424.55
  BottomLayer w6: v1@7755,7464 cw(c7755,7451.93) 7763.54,7460.46 cw(c7772.07,7469) v1@7760,7469 ; v1(7755,7469) 7780,7444 v1(8041.04,7444)
NetR50_1: R74.1 U11.V23 | length 567.3
  TopLayer w6: v1(8081.15,7522) U11.V23@8099.86,7503.29
  BottomLayer w6: R74.1@7626,7674 7695,7674 7825,7544 8059.15,7544 v1(8081.15,7522) ; R74.1@7638.74,7669.76 cw(c7648.99,7659.51) 7648.99,7674 cw(c7648.99,7688.49) R74.1@7638.74,7678.24
NetR50_2: R74.2 U11.V24 | length 496
  TopLayer w6: v1(8041.78,7522) U11.V24@8060.49,7503.29
  BottomLayer w6: R74.2@7638.74,7633.76 cw(c7648.99,7623.51) 7648.99,7638 cw(c7648.99,7652.49) R74.2@7638.74,7642.24 ; R74.2@7643,7638 7696,7638 7812,7522 v1(8041.78,7522)
NetR50_3: R74.3 U11.U23 | length 553.8
  TopLayer w6: v1(8080.78,7483) U11.U23@8099.86,7463.92
  BottomLayer w6: R74.3@7626,7602 7696,7602 7793,7505 8058.78,7505 v1(8080.78,7483) ; R74.3@7638.74,7597.76 cw(c7648.99,7587.51) 7648.99,7602 cw(c7648.99,7616.49) R74.3@7638.74,7606.24
NetR50_4: R74.4 U11.U24 | length 499.5
  TopLayer w6: v1(8041.41,7483) U11.U24@8060.49,7463.92
  BottomLayer w6: R74.4@7626,7566 7701,7566 7784,7483 v1(8041.41,7483) ; R74.4@7638.74,7561.76 cw(c7648.99,7551.51) 7648.99,7566 cw(c7648.99,7580.49) R74.4@7638.74,7570.24
NetR51_1: R37.1 U11.U26 | length 407.5
  TopLayer w6: R37.1@7626,7534 7723,7534 7793.08,7463.92 U11.U26@7981.75,7463.92 ; R37.1@7638.74,7529.76 cw(c7648.99,7519.51) 7648.99,7534 cw(c7648.99,7548.49) R37.1@7638.74,7538.24
NetR51_2: R37.2 U11.U25 | length 461.8
  TopLayer w6: R37.2@7626,7570 7711,7570 7798,7483 8002.04,7483 U11.U25@8021.12,7463.92 ; R37.2@7638.74,7565.76 cw(c7648.99,7555.51) 7648.99,7570 cw(c7648.99,7584.49) R37.2@7638.74,7574.24
NetR51_3: R37.3 U11.V26 | length 421
  TopLayer w6: R37.3@7626,7606 7704,7606 7806.71,7503.29 U11.V26@7981.75,7503.29 ; R37.3@7638.74,7601.76 cw(c7648.99,7591.51) 7648.99,7606 cw(c7648.99,7620.49) R37.3@7638.74,7610.24
NetR51_4: R37.4 U11.V25 | length 475.3
  TopLayer w6: R37.4@7626,7642 7698,7642 7818,7522 8002.41,7522 U11.V25@8021.12,7503.29 ; R37.4@7638.74,7637.76 cw(c7648.99,7627.51) 7648.99,7642 cw(c7648.99,7656.49) R37.4@7638.74,7646.24
NetR52_1: R71.1 U11.K23 | length 527.1
  TopLayer w6: v1(8079.19,7209) U11.K23@8099.86,7188.33
  BottomLayer w6: R71.1@7626,7194 7673,7194 7682,7203 7947,7203 7972,7228 8060.19,7228 v1(8079.19,7209) ; R71.1@7638.74,7189.76 cw(c7648.99,7179.51) 7648.99,7194 cw(c7648.99,7208.49) R71.1@7638.74,7198.24
NetR52_2: R71.2 U11.K24 | length 486.9
  TopLayer w6: v1(8039.82,7209) U11.K24@8060.49,7188.33
  BottomLayer w6: R71.2@7626,7158 7677,7158 7704,7185 7968,7185 7992,7209 v1(8039.82,7209) ; R71.2@7638.74,7153.76 cw(c7648.99,7143.51) 7648.99,7158 cw(c7648.99,7172.49) R71.2@7638.74,7162.24
NetR52_3: R71.3 U11.J24 | length 485
  TopLayer w6: v1(8040.45,7169) U11.J24@8060.49,7148.96
  BottomLayer w6: R71.3@7626,7122 7677,7122 7724,7169 v1(8040.45,7169) ; R71.3@7638.74,7117.76 cw(c7648.99,7107.51) 7648.99,7122 cw(c7648.99,7136.49) R71.3@7638.74,7126.24
NetR52_4: R71.4 U11.J25 | length 462.2
  TopLayer w6: v1(8000.16,7128) U11.J25@8021.12,7148.96
  BottomLayer w6: R71.4@7626,7086 7679,7086 7743,7150 7939,7150 7961,7128 v1(8000.16,7128) ; R71.4@7638.74,7081.76 cw(c7648.99,7071.51) 7648.99,7086 cw(c7648.99,7100.49) R71.4@7638.74,7090.24
NetR54_1: R35.1 U11.M25 | length 445.2
  TopLayer w6: R35.1@7626,7201 7817,7201 7864,7248 8002.05,7248 U11.M25@8021.12,7267.07 ; R35.1@7638.74,7196.76 cw(c7648.99,7186.51) 7648.99,7201 cw(c7648.99,7215.49) R35.1@7638.74,7205.24
NetR54_2: R35.2 U11.M26 | length 391
  TopLayer w6: R35.2@7626,7237 7819,7237 7849.07,7267.07 U11.M26@7981.75,7267.07 ; R35.2@7638.74,7232.76 cw(c7648.99,7222.51) 7648.99,7237 cw(c7648.99,7251.49) R35.2@7638.74,7241.24
NetR54_3: R35.3 U11.N26 | length 408.6
  TopLayer w6: R35.3@7626,7273 7680,7273 7733,7326 7919,7326 7938.56,7306.44 U11.N26@7981.75,7306.44 ; R35.3@7638.74,7268.76 cw(c7648.99,7258.51) 7648.99,7273 cw(c7648.99,7287.49) R35.3@7638.74,7277.24
NetR54_4: R35.4 U11.P26 | length 393.7
  TopLayer w6: R35.4@7626,7309 7670,7309 7706.81,7345.81 U11.P26@7981.75,7345.81 ; R35.4@7638.74,7304.76 cw(c7648.99,7294.51) 7648.99,7309 cw(c7648.99,7323.49) R35.4@7638.74,7313.24
NetR55_1: R27.1 U11.J26 | length 795.1
  TopLayer w6: R27.1@7379.46,6934 7452.46,7007 7671,7007 7706,7042 7796,7042 7902.96,7148.96 U11.J26@7981.75,7148.96 ; R27.1@7381.43,6944.69 ccw(c7381.43,6965.73) R27.1@7396.31,6950.85 ; R27.1@7381.43,6950.69 ccw(c7381.43,6986.21) 7406.56,6961.09 ; R27.1@7392.12,6934 cw(c7422.67,6934) 7401.07,6955.6 ; R27.1@7398.12,6934 cw(c7443.15,6934) 7411.31,6965.84
NetR56_2: R64.2 S1.1 | length 589.1
  BottomLayer w8: S1.1@4916.95,6359.95 cw(c4873.37,6316.37) 4935,6316.37 cw(c4996.63,6316.37) S1.1@4953.05,6359.95 ; S1.1@4922.61,6365.61 cw(c4892.68,6335.68) 4935,6335.68 cw(c4977.32,6335.68) S1.1@4947.39,6365.61 ; 4935,6261.64 ccw(c4983.21,6261.64) R64.2@4949.12,6227.55 ; 4935,6280.96 ccw(c5002.52,6280.96) R64.2@4954.78,6233.21 ; 4935,6300.27 ccw(c5021.84,6300.27) R64.2@4960.43,6238.87 ; 4935,6319.58 ccw(c5041.15,6319.58) R64.2@4966.09,6244.52 ; S1.1@4935,6378 4935,6251.46 R64.2@4955,6231.46 ; R64.2@4939.75,6237.11 ccw(c4925.94,6240.43) 4935.99,6250.48 ccw(c4944.39,6258.89) R64.2@4948.97,6247.91
NetR57_2: R63.2 S1.2 | length 369.3
  BottomLayer w8: S1.2@4816.95,6359.95 cw(c4773.37,6316.37) 4835,6316.37 cw(c4896.63,6316.37) S1.2@4853.05,6359.95 ; S1.2@4822.61,6365.61 cw(c4792.68,6335.68) 4835,6335.68 cw(c4877.32,6335.68) S1.2@4847.39,6365.61 ; R63.2@4823.91,6244.52 ccw(c4797.13,6271.3) 4835,6271.3 ccw(c4872.87,6271.3) R63.2@4846.09,6244.52 ; R63.2@4835,6231.46 S1.2@4835,6378
NetR65_2: R50.2 U13.20 | length 239.6
  TopLayer w12: R50.2@8360,9453.46 8403.54,9497 8447,9497 8460,9484 U13.20@8460,9439.84 ; R50.2@8360,9469.12 ccw(c8360,9506.91) 8386.72,9480.19 ; R50.2@8373.69,9455.43 cw(c8401.97,9455.43) 8381.97,9475.43 ; 8450.63,9493.37 cw(c8432.54,9475.28) U13.20@8458.13,9475.28
NetR66_1: R44.1 U13.19 | length 381.8
  TopLayer w12: R44.1@8260,9453.46 8335.54,9529 8458,9529 8485.59,9501.41 U13.19@8485.59,9439.84 ; R44.1@8260,9469.12 ccw(c8260,9506.91) 8286.72,9480.19 ; R44.1@8273.69,9455.43 cw(c8301.97,9455.43) 8281.97,9475.43
NetR76_1: R49.1 U12.3 | length 624.5
  TopLayer w8: U12.3@8434.99,8322.45 cw(c8374.61,8262.07) 8460,8262.07 cw(c8545.39,8262.07) U12.3@8485.01,8322.45 ; U12.3@8440.65,8328.11 cw(c8393.92,8281.39) 8460,8281.39 cw(c8526.08,8281.39) U12.3@8479.35,8328.11 ; U12.3@8446.3,8333.77 cw(c8413.24,8300.7) 8460,8300.7 cw(c8506.76,8300.7) U12.3@8473.7,8333.77 ; R49.1@8448.91,8126.52 ccw(c8422.13,8153.3) 8460,8153.3 ccw(c8497.87,8153.3) R49.1@8471.09,8126.52 ; R49.1@8460,8113.46 U12.3@8460,8367.15
NetR79_2: R55.2 U11.B4 | length 654.7
  TopLayer w6: U11.B4@8847.89,6873.37 8868,6853.26 8868,6818 8850,6800 8850,6700 8862,6688 9025,6688 9051,6662 9051,6595.54 R55.2@9106.54,6540 ; 9074.69,6571.84 cw(c9042.85,6540) R55.2@9087.88,6540 ; 9079.44,6567.09 ccw(c9104.57,6592.21) R55.2@9104.57,6556.69 ; 9084.93,6561.6 cw(c9063.33,6540) R55.2@9093.88,6540 ; R55.2@9089.69,6556.85 ccw(c9104.57,6571.73) R55.2@9104.57,6550.69
NetR80_1: R82.1 U11.AE4 | length 375
  TopLayer w6: v1@8824.46,8077.93 cw(c8815.93,8069.39) 8828,8069.39 cw(c8840.07,8069.39) v1@8831.54,8077.93 ; v1(8828,8081.46) 8828,7798.77 U11.AE4@8847.89,7778.88
  BottomLayer w6: v1(8828,8081.46) R82.1@8846.54,8100 ; R82.1@8828,8086.46 ccw(c8828,8098.54) 8836.54,8090 ccw(c8845.07,8081.46) R82.1@8833,8081.46
NetR81_1: R28.1 U8.4 | length 484.4
  TopLayer w6: U8.4@7218.97,7875.68 ccw(c7203.93,7890.72) 7225.2,7890.72 ccw(c7246.47,7890.72) U8.4@7231.43,7875.68 ; U8.4@7225.2,7841.89 7225.2,7891.8 7184,7933 7184,8082 7202,8100 R28.1@7266.54,8100 ; R28.1@7252.77,8088.2 ccw(c7224.29,8059.72) 7224.29,8100 ccw(c7224.29,8140.28) R28.1@7252.77,8111.8 ; R28.1@7257.01,8092.44 ccw(c7238.77,8074.2) 7238.77,8100 ccw(c7238.77,8125.8) R28.1@7257.01,8107.56
NetR81_2: R28.2 R52.2 U11.C5 | length 5026
  TopLayer w6: R28.2@7333.46,8100 7345.46,8088 7503,8088 7642,8227 7794,8227 v1(7813,8246) ; R28.2@7334.5,8099.07 ccw(c7361.23,8125.8) 7361.23,8088 ; R28.2@7338.75,8103.31 ccw(c7375.71,8140.28) 7375.71,8088 ; R28.2@7342.99,8107.56 ccw(c7390.2,8154.77) 7390.2,8088 ; R28.2@7347.23,8111.8 ccw(c7404.68,8169.25) 7404.68,8088 ; v1@7808,8246 cw(c7795.93,8246) 7804.46,8237.46 cw(c7813,8228.93) v1@7813,8241 ; U11.C5@8808.52,6912.74 8788,6892.22 8788,6678.54 8987.54,6479 9217,6479 9260,6522 v2(9260,6703) ; 8894.69,6571.84 cw(c8862.85,6540) R52.2@8907.88,6540 ; 8899.44,6567.09 ccw(c8924.57,6592.21) R52.2@8924.57,6556.69 ; 8904.93,6561.6 cw(c8883.33,6540) R52.2@8913.88,6540 ; R52.2@8909.69,6556.85 ccw(c8924.57,6571.73) R52.2@8924.57,6550.69 ; R52.2@8928.5,6523.31 cw(c8928.5,6487.79) 8953.63,6512.91 ; R52.2@8928.5,6529.31 cw(c8928.5,6508.27) R52.2@8943.38,6523.15 ; R52.2@8939.19,6540 ccw(c8969.74,6540) 8948.14,6518.4 ; R52.2@8945.19,6540 ccw(c8990.22,6540) 8958.38,6508.16 ; v2@9255.05,6698.05 cw(c9243.1,6686.1) 9260,6686.1 cw(c9276.9,6686.1) v2@9264.95,6698.05
  BottomLayer w6: v1(7813,8246) 7964,8246 8024,8186 8568,8186 8709,8045 9293,8045 9384,7954 9384,7729 9366,7711 9366,6809 v2(9260,6703) ; v1@7816.54,8242.46 cw(c7825.07,8233.93) 7825.07,8246 cw(c7825.07,8258.07) v1@7816.54,8249.54 ; v2@9260,6710 ccw(c9260,6726.9) 9271.95,6714.95 ccw(c9283.9,6703) v2@9267,6703
NetR82_1: R54.1 U15.3 | length 584.5
  TopLayer w8: U15.3@8974.99,8302.45 cw(c8914.61,8242.07) 9000,8242.07 cw(c9085.39,8242.07) U15.3@9025.01,8302.45 ; U15.3@8980.65,8308.11 cw(c8933.92,8261.39) 9000,8261.39 cw(c9066.08,8261.39) U15.3@9019.35,8308.11 ; U15.3@8986.3,8313.77 cw(c8953.24,8280.7) 9000,8280.7 cw(c9046.76,8280.7) U15.3@9013.7,8313.77 ; R54.1@8988.91,8166.52 ccw(c8962.13,8193.3) 9000,8193.3 ccw(c9037.87,8193.3) R54.1@9011.09,8166.52 ; R54.1@9000,8153.46 U15.3@9000,8367.15
NetR84_2: R53.2 U11.B5 | length 424.4
  TopLayer w6: U11.B5@8808.52,6873.37 8828,6853.89 8828,6679 8867,6640 R53.2@8926.54,6640 R53.2@8926.54,6643.46 ; R53.2@8912.77,6628.2 ccw(c8884.29,6599.72) 8884.29,6640 ccw(c8884.29,6680.28) R53.2@8912.77,6651.8 ; R53.2@8917.01,6632.44 ccw(c8898.77,6614.2) 8898.77,6640 ccw(c8898.77,6665.8) R53.2@8917.01,6647.56
NetS2_2: S2.2 U8.3 | length 871.4
  TopLayer w12: U8.3@7221.09,7991.67 ccw(c7211.17,8001.59) 7225.2,8001.59 ccw(c7239.23,8001.59) U8.3@7229.31,7991.67 ; U8.3@7225.2,7960 v1(7225.2,8027.2)
  BottomLayer w12: S2.2@7170,8673.8 cw(c7170,8616.99) 7210.16,8657.16 cw(c7250.33,8697.32) S2.2@7193.53,8697.32 ; S2.2@7170,8697.32 7225.2,8642.13 v1(7225.2,8027.2)
NSTATUS: R65.1 U1.146 | length 275.1
  TopLayer w12: U1.146@4937.69,8342.58 4990.42,8342.58 v3(5005,8328) ; v3@4999,8328 ccw(c4984.51,8328) 4994.76,8338.24 ccw(c5005,8348.49) v3@5005,8334
  BottomLayer w12: v3@5009.24,8323.76 cw(c5019.49,8313.51) 5019.49,8328 cw(c5019.49,8342.49) v3@5009.24,8332.24 ; 5032.83,8328 ccw(c5032.83,8369.96) R65.1@5063.34,8341.16 ; R65.1@5054.62,8349.39 cw(c5005,8396.22) v3(5005,8328) 5054.54,8328 R65.1@5066.54,8340
OUT1+: C3.1 U3.B9 | length 1784
  TopLayer w8: C3.1@4553.46,9380 4584.46,9411 5123,9411 5390,9678 5927,9678 5971,9634 5971,9533.59 U3.B9@5990.96,9513.63 ; C3.1@4555.43,9395.68 ccw(c4555.43,9428.8) 4578.85,9405.38 ; C3.1@4563.12,9380 cw(c4586.42,9380) C3.1@4569.94,9396.48 ; C3.1@4571.12,9380 cw(c4613.74,9380) 4583.6,9410.14 ; U3.B9@5986.1,9513.63 ccw(c5974.37,9513.63) 5982.67,9521.92 ccw(c5990.96,9530.22) U3.B9@5990.96,9518.49
OUT1-: C4.1 U3.A9 | length 1771.3
  TopLayer w8: C4.1@4553.46,9480 4599.17,9434.3 5116.3,9434.3 5378,9696 5935,9696 5990.96,9640.04 U3.A9@5990.96,9553 ; C4.1@4555.43,9464.32 cw(c4555.43,9431.2) 4578.85,9454.62 ; C4.1@4563.12,9480 ccw(c4586.42,9480) C4.1@4569.94,9463.52 ; C4.1@4571.12,9480 ccw(c4613.74,9480) 4583.6,9449.86 ; U3.A9@5987.53,9556.44 ccw(c5979.23,9564.73) 5990.96,9564.73 ccw(c6002.69,9564.73) U3.A9@5994.4,9556.44
OUT2+: U3.A4
OUT2-: U3.B4 | length 50.3
  TopLayer w6: U3.B4@5794.11,9513.63 5814,9533.52 ; U3.B4@5794.11,9519.49 ccw(c5794.11,9533.63) 5804.11,9523.63 ccw(c5814.11,9513.63) U3.B4@5799.97,9513.63
P\C\I\6\6\: R80.1 U11.AD1 | length 756.6
  TopLayer w6: v1@8943.46,7981.54 ccw(c8934.93,7990.07) 8947,7990.07 ccw(c8959.07,7990.07) v1@8950.54,7981.54 ; v1@8943.46,8162.93 cw(c8934.93,8154.39) 8947,8154.39 cw(c8959.07,8154.39) v1@8950.54,8162.93 ; v1(8947,7758.51) U11.AD1@8966,7739.51 ; v1(8947,7978) v1(8947,8166.46)
  BottomLayer w6: R80.1@8913.46,8200 v1(8947,8166.46) ; R80.1@8915.43,8183.31 cw(c8915.43,8147.79) 8940.56,8172.91 ; R80.1@8915.43,8189.31 cw(c8915.43,8168.27) R80.1@8930.31,8183.15 ; R80.1@8926.12,8200 ccw(c8956.67,8200) 8935.07,8178.4 ; R80.1@8932.12,8200 ccw(c8977.15,8200) v1@8945.31,8168.16 ; v1@8942,7978 cw(c8929.93,7978) 8938.46,7969.46 cw(c8947,7960.93) v1@8947,7973 ; v1@8942,8166.46 ccw(c8929.93,8166.46) 8938.46,8175 ccw(c8947,8183.54) v1@8947,8171.46 ; v1(8947,7758.51) 8905.49,7758.51 8861.99,7802.01 8861.99,7892.99 v1(8947,7978)
P_AD0: U11.Y3 U21.29 | length 330.3
  TopLayer w6: U11.Y3@8887.26,7582.03 v1(8908,7562)
  BottomLayer w6: v1(8908,7562) 9053.99,7562 9090,7525.98 U21.29@9185.04,7525.98 ; U21.29@9149.4,7524.21 ccw(c9145.12,7519.92) 9145.12,7525.99 ccw(c9145.12,7532.05) U21.29@9149.4,7527.76
P_AD1: U11.AA1 U21.35 | length 275.9
  TopLayer w6: U11.AA1@8966,7621.4 9008.4,7621.4 v1(9031.09,7644.1) ; v1@9026.09,7644.1 cw(c9014.02,7644.1) 9022.56,7635.56 cw(c9031.09,7627.02) v1@9031.09,7639.1
  BottomLayer w6: v1(9031.09,7644.1) U21.35@9185.04,7644.1 ; v1@9034.63,7640.56 cw(c9043.17,7632.02) 9043.17,7644.1 cw(c9043.17,7656.17) v1@9034.63,7647.63 ; U21.35@9149.4,7642.32 ccw(c9145.12,7638.03) 9145.12,7644.1 ccw(c9145.12,7650.16) U21.35@9149.4,7645.87
P_AD2: U11.Y4 U21.28 | length 378
  TopLayer w6: U11.Y4@8847.89,7582.03 v1(8867.92,7562)
  BottomLayer w6: v1(8867.92,7562) 8885.92,7544 9046,7544 9083.7,7506.3 U21.28@9185.04,7506.3 ; U21.28@9149.4,7504.52 ccw(c9145.12,7500.24) 9145.12,7506.3 ccw(c9145.12,7512.36) U21.28@9149.4,7508.08
P_AD3: U11.Y2 U21.34 | length 323.4
  TopLayer w6: U11.Y2@8926.63,7582.03 8945.6,7601 9037,7601 v1(9060.41,7624.41) ; v1@9055.41,7624.41 cw(c9043.34,7624.41) 9051.87,7615.87 cw(c9060.41,7607.34) v1@9060.41,7619.41
  BottomLayer w6: v1(9060.41,7624.41) U21.34@9185.04,7624.41 ; v1@9063.95,7620.87 cw(c9072.48,7612.34) 9072.48,7624.41 cw(c9072.48,7636.48) v1@9063.95,7627.95 ; U21.34@9149.4,7622.63 ccw(c9145.12,7618.35) 9145.12,7624.41 ccw(c9145.12,7630.47) U21.34@9149.4,7626.19
P_AD4: U11.W3 U21.27 | length 330.5
  TopLayer w6: U11.W3@8887.26,7542.66 v1(8905.92,7524)
  BottomLayer w6: v1(8905.92,7524) 9039,7524 9076.39,7486.61 U21.27@9185.04,7486.61 ; U21.27@9149.4,7484.84 ccw(c9145.12,7480.55) 9145.12,7486.62 ccw(c9145.12,7492.68) U21.27@9149.4,7488.39
P_AD5: U11.Y1 U21.33 | length 275.9
  TopLayer w6: U11.Y1@8966,7582.03 9047.03,7582.03 9069.73,7604.73 v1(9128.73,7604.73) ; v1@9125.19,7601.19 ccw(c9116.65,7592.65) 9116.65,7604.73 ccw(c9116.65,7616.8) v1@9125.19,7608.26
  BottomLayer w6: v1(9128.73,7604.73) U21.33@9185.04,7604.73 ; v1@9132.26,7601.19 cw(c9140.8,7592.65) 9140.8,7604.73 cw(c9140.8,7616.8) v1@9132.26,7608.26 ; U21.33@9149.4,7602.95 ccw(c9145.12,7598.66) 9145.12,7604.73 ccw(c9145.12,7610.79) U21.33@9149.4,7606.5
P_AD6: U11.W4 U21.26 | length 378
  TopLayer w6: U11.W4@8847.89,7542.66 v1(8866.55,7524)
  BottomLayer w6: v1(8866.55,7524) 8886.55,7504 9032,7504 9069.07,7466.93 U21.26@9185.04,7466.93 ; U21.26@9149.4,7465.15 ccw(c9145.12,7460.87) 9145.12,7466.93 ccw(c9145.12,7472.99) U21.26@9149.4,7468.71
P_AD7: U11.W2 U21.31 | length 335.7
  TopLayer w6: U11.W2@8926.63,7542.66 8946.97,7563 9057,7563 v1(9080,7586) ; v1@9075,7586 cw(c9062.93,7586) 9071.46,7577.46 cw(c9080,7568.93) v1@9080,7581
  BottomLayer w6: v1(9080,7586) 9100,7586 9120.65,7565.35 U21.31@9185.04,7565.35 U21.31@9182.68,7563 ; v1@9083.54,7582.46 cw(c9092.07,7573.93) 9092.07,7586 cw(c9092.07,7598.07) v1@9083.54,7589.54 ; U21.31@9149.4,7563.58 ccw(c9145.12,7559.29) 9145.12,7565.36 ccw(c9145.12,7571.42) U21.31@9149.4,7567.13
P_AD8: U11.V2 U21.30 | length 323.4
  TopLayer w6: U11.V2@8926.63,7503.29 8947.34,7524 9109,7524 v1(9130.67,7545.67) ; v1@9125.67,7545.67 cw(c9113.6,7545.67) 9122.13,7537.13 cw(c9130.67,7528.6) v1@9130.67,7540.67
  BottomLayer w6: v1(9130.67,7545.67) U21.30@9185.04,7545.67 ; v1@9134.21,7542.13 cw(c9142.74,7533.6) 9142.74,7545.67 cw(c9142.74,7557.74) v1@9134.21,7549.21 ; U21.30@9149.4,7543.89 ccw(c9145.12,7539.61) 9145.12,7545.67 ccw(c9145.12,7551.73) U21.30@9149.4,7547.45
P_AD9: U11.V3 U21.25 | length 330.5
  TopLayer w6: U11.V3@8887.26,7503.29 v1(8906.55,7484)
  BottomLayer w6: v1(8906.55,7484) 9032,7484 9068.75,7447.24 U21.25@9185.04,7447.24 ; U21.25@9149.4,7445.47 ccw(c9145.12,7441.18) 9145.12,7447.24 ccw(c9145.12,7453.31) U21.25@9149.4,7449.02
P_AD10: U11.V1 U16.25 | length 282.6
  TopLayer w6: U11.V1@8966,7503.29 9010.71,7503.29 9141.25,7372.76 U16.25@9185.04,7372.76 ; U16.25@9149.4,7370.98 ccw(c9145.12,7366.69) 9145.12,7372.76 ccw(c9145.12,7378.82) U16.25@9149.4,7374.53
P_AD11: U11.U4 U20.44 | length 405.8
  TopLayer w6: U11.U4@8847.89,7463.92 v1(8867.81,7444)
  BottomLayer w6: v1(8867.81,7444) 8885.81,7426 8960,7426 8981,7405 9029,7405 9112.74,7321.26 U20.44@9185.04,7321.26 ; U20.44@9149.4,7319.48 ccw(c9145.12,7315.2) 9145.12,7321.26 ccw(c9145.12,7327.32) U20.44@9149.4,7323.04
P_AD12: U11.U2 U16.26 | length 330.5
  TopLayer w6: U11.U2@8926.63,7463.92 8946.71,7484 9006,7484 9136.93,7353.07 U16.26@9185.04,7353.07 ; U16.26@9149.4,7351.29 ccw(c9145.12,7347.01) 9145.12,7353.07 ccw(c9145.12,7359.13) U16.26@9149.4,7354.85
